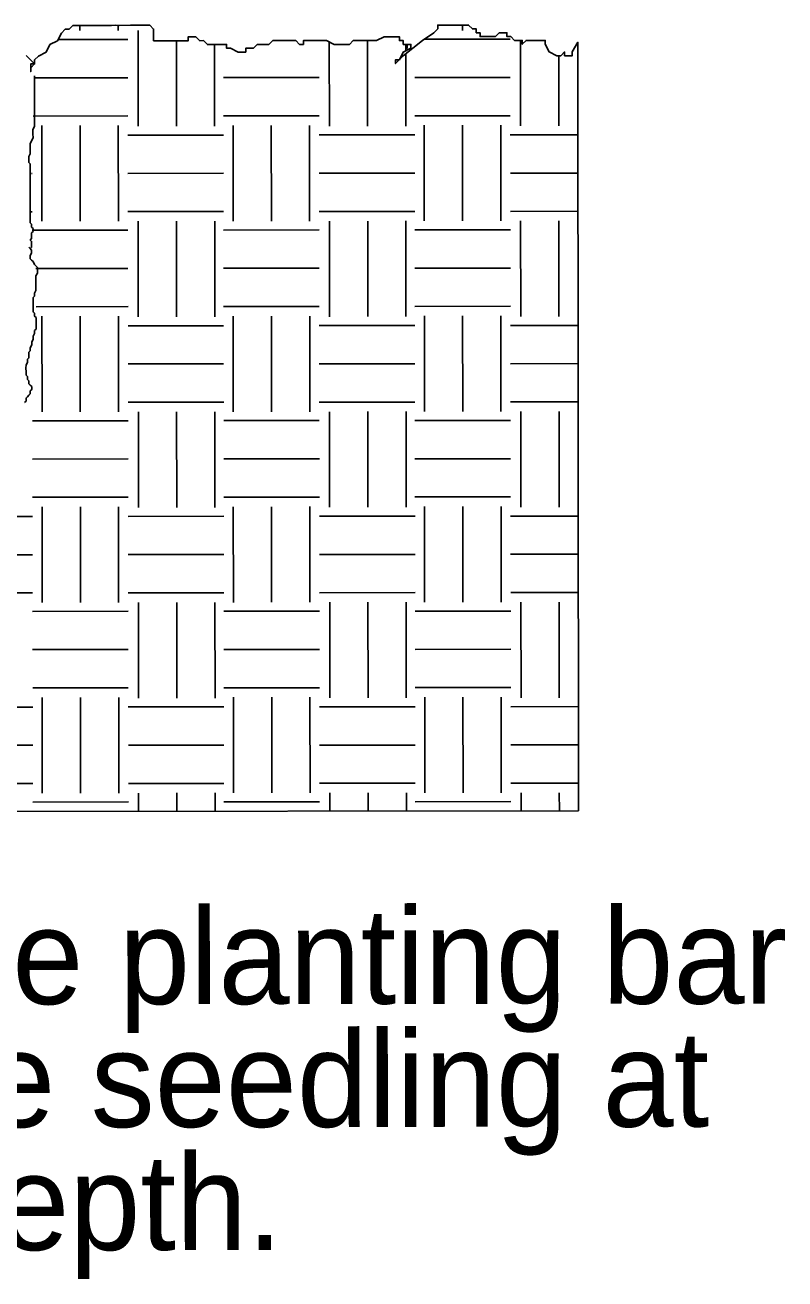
# Model space of a CAD drawing. Extents: x 1728110 to 1729925, y 1284214 to 1285339.
# Drawn here: x 1728835 to 1728889.8, y 1284892.4 to 1284982.8 of the extents above; entities that cross this region are included whole.
import ezdxf

# ---------------------------------------------------------------- set-up
doc = ezdxf.new("R2010")
doc.units = 0
doc.layers.add('Reforestation Detail CELL', color=7, linetype='Continuous')

msp = doc.modelspace()

# ---------------------------------------------------------------- linework, layer by layer
at = {"layer": 'Reforestation Detail CELL'}
for p, q in [((1728838.954, 1284982.743), (1728838.955, 1284982.364)), ((1728841.711, 1284982.746), (1728841.711, 1284982.366)), ((1728866.513, 1284982.764), (1728866.513, 1284982.385)), ((1728837.389, 1284981.722), (1728842.4, 1284981.726)), ((1728843.14, 1284982.367), (1728843.145, 1284975.478)), ((1728845.897, 1284981.64), (1728845.901, 1284975.48)), ((1728859.675, 1284981.651), (1728859.68, 1284975.49)), ((1728863.763, 1284981.742), (1728869.959, 1284981.747)), ((1728870.699, 1284981.659), (1728870.703, 1284975.498)), ((1728848.652, 1284981.366), (1728848.657, 1284975.482)), ((1728856.92, 1284981.545), (1728856.924, 1284975.488)), ((1728862.432, 1284981.376), (1728862.432, 1284980.915)), ((1728862.433, 1284980.693), (1728862.436, 1284975.493)), ((1728874.836, 1284981.524), (1728874.877, 1284926.15)), ((1728873.456, 1284980.553), (1728873.46, 1284975.501)), ((1728835.654, 1284978.965), (1728842.402, 1284978.971)), ((1728849.292, 1284978.976), (1728856.182, 1284978.981)), ((1728863.071, 1284978.986), (1728869.961, 1284978.991)), ((1728835.574, 1284976.209), (1728842.404, 1284976.215)), ((1728849.293, 1284976.22), (1728856.184, 1284976.225)), ((1728863.073, 1284976.23), (1728869.963, 1284976.235)), ((1728836.204, 1284975.521), (1728836.209, 1284968.631)), ((1728838.96, 1284975.522), (1728838.965, 1284968.633)), ((1728841.716, 1284975.525), (1728841.721, 1284968.635)), ((1728849.983, 1284975.531), (1728849.989, 1284968.641)), ((1728852.739, 1284975.534), (1728852.745, 1284968.643)), ((1728855.495, 1284975.535), (1728855.501, 1284968.646)), ((1728863.763, 1284975.542), (1728863.767, 1284968.652)), ((1728866.518, 1284975.544), (1728866.524, 1284968.654)), ((1728869.274, 1284975.546), (1728869.279, 1284968.656)), ((1728842.405, 1284974.836), (1728849.295, 1284974.841)), ((1728856.184, 1284974.847), (1728863.075, 1284974.852)), ((1728869.964, 1284974.857), (1728874.841, 1284974.861)), ((1728835.453, 1284972.075), (1728835.518, 1284972.075)), ((1728842.407, 1284972.08), (1728849.296, 1284972.085)), ((1728856.187, 1284972.091), (1728863.076, 1284972.096)), ((1728869.966, 1284972.102), (1728874.843, 1284972.105)), ((1728835.372, 1284969.32), (1728835.52, 1284969.319)), ((1728842.409, 1284969.324), (1728849.299, 1284969.329)), ((1728856.189, 1284969.335), (1728863.078, 1284969.341)), ((1728869.968, 1284969.345), (1728874.845, 1284969.349)), ((1728843.15, 1284968.636), (1728843.155, 1284961.747)), ((1728845.906, 1284968.638), (1728845.911, 1284961.749)), ((1728848.662, 1284968.64), (1728848.667, 1284961.75)), ((1728849.3, 1284968.001), (1728856.189, 1284968.006)), ((1728856.929, 1284968.647), (1728856.935, 1284961.757)), ((1728859.685, 1284968.648), (1728859.691, 1284961.759)), ((1728862.441, 1284968.651), (1728862.446, 1284961.761)), ((1728863.08, 1284968.011), (1728869.969, 1284968.016)), ((1728870.708, 1284968.657), (1728870.714, 1284961.767)), ((1728873.465, 1284968.659), (1728873.469, 1284961.769)), ((1728835.52, 1284967.99), (1728842.41, 1284967.994)), ((1728835.783, 1284965.234), (1728842.412, 1284965.239)), ((1728849.302, 1284965.245), (1728856.192, 1284965.25)), ((1728863.081, 1284965.255), (1728869.971, 1284965.26)), ((1728835.785, 1284962.478), (1728842.414, 1284962.484)), ((1728836.214, 1284961.789), (1728836.219, 1284954.9)), ((1728838.97, 1284961.791), (1728838.975, 1284954.902)), ((1728841.726, 1284961.794), (1728841.731, 1284954.904)), ((1728849.305, 1284962.489), (1728856.194, 1284962.494)), ((1728849.994, 1284961.8), (1728849.999, 1284954.91)), ((1728852.75, 1284961.801), (1728852.755, 1284954.912)), ((1728855.505, 1284961.804), (1728855.511, 1284954.914)), ((1728863.083, 1284962.499), (1728869.974, 1284962.504)), ((1728863.773, 1284961.81), (1728863.778, 1284954.921)), ((1728866.529, 1284961.813), (1728866.534, 1284954.922)), ((1728869.285, 1284961.814), (1728869.29, 1284954.925)), ((1728842.416, 1284961.105), (1728849.305, 1284961.11)), ((1728856.195, 1284961.115), (1728863.084, 1284961.12)), ((1728869.974, 1284961.126), (1728874.852, 1284961.13)), ((1728842.417, 1284958.349), (1728849.307, 1284958.354)), ((1728856.197, 1284958.359), (1728863.086, 1284958.364)), ((1728869.977, 1284958.37), (1728874.853, 1284958.374)), ((1728842.419, 1284955.593), (1728849.309, 1284955.598)), ((1728856.199, 1284955.603), (1728863.088, 1284955.61)), ((1728869.979, 1284955.614), (1728874.855, 1284955.618)), ((1728843.16, 1284954.905), (1728843.165, 1284948.015)), ((1728845.916, 1284954.907), (1728845.921, 1284948.018)), ((1728848.672, 1284954.909), (1728848.677, 1284948.019)), ((1728856.94, 1284954.915), (1728856.945, 1284948.026)), ((1728859.696, 1284954.917), (1728859.701, 1284948.028)), ((1728862.451, 1284954.92), (1728862.457, 1284948.029)), ((1728870.719, 1284954.926), (1728870.724, 1284948.036)), ((1728873.475, 1284954.928), (1728873.48, 1284948.038)), ((1728835.53, 1284954.258), (1728842.421, 1284954.263)), ((1728849.31, 1284954.269), (1728856.201, 1284954.274)), ((1728863.09, 1284954.28), (1728869.979, 1284954.285)), ((1728835.533, 1284951.502), (1728842.422, 1284951.507)), ((1728849.312, 1284951.513), (1728856.202, 1284951.518)), ((1728863.092, 1284951.524), (1728869.982, 1284951.529)), ((1728835.535, 1284948.746), (1728842.424, 1284948.752)), ((1728849.315, 1284948.757), (1728856.204, 1284948.763)), ((1728863.094, 1284948.768), (1728869.984, 1284948.773)), ((1728832.278, 1284947.367), (1728835.535, 1284947.369)), ((1728836.224, 1284948.058), (1728836.229, 1284941.168)), ((1728838.98, 1284948.06), (1728838.986, 1284941.171)), ((1728841.736, 1284948.062), (1728841.741, 1284941.173)), ((1728842.426, 1284947.374), (1728849.315, 1284947.379)), ((1728850.004, 1284948.068), (1728850.009, 1284941.179)), ((1728852.76, 1284948.07), (1728852.765, 1284941.181)), ((1728855.516, 1284948.073), (1728855.521, 1284941.183)), ((1728856.205, 1284947.384), (1728863.095, 1284947.389)), ((1728863.783, 1284948.079), (1728863.789, 1284941.189)), ((1728866.539, 1284948.082), (1728866.545, 1284941.191)), ((1728869.295, 1284948.083), (1728869.3, 1284941.193)), ((1728869.984, 1284947.394), (1728874.862, 1284947.399)), ((1728828.648, 1284944.608), (1728835.538, 1284944.613)), ((1728842.428, 1284944.618), (1728849.317, 1284944.623)), ((1728856.207, 1284944.628), (1728863.097, 1284944.633)), ((1728869.987, 1284944.638), (1728874.864, 1284944.643)), ((1728828.651, 1284941.852), (1728835.54, 1284941.857)), ((1728842.429, 1284941.862), (1728849.32, 1284941.867)), ((1728856.209, 1284941.872), (1728863.099, 1284941.877)), ((1728869.989, 1284941.882), (1728874.865, 1284941.887)), ((1728843.171, 1284941.174), (1728843.176, 1284934.284)), ((1728845.927, 1284941.176), (1728845.931, 1284934.286)), ((1728848.682, 1284941.178), (1728848.688, 1284934.288)), ((1728856.95, 1284941.184), (1728856.955, 1284934.294)), ((1728859.706, 1284941.186), (1728859.711, 1284934.297)), ((1728862.462, 1284941.188), (1728862.467, 1284934.298)), ((1728870.729, 1284941.194), (1728870.735, 1284934.305)), ((1728873.485, 1284941.196), (1728873.491, 1284934.307)), ((1728835.541, 1284940.527), (1728842.431, 1284940.532)), ((1728849.32, 1284940.537), (1728856.21, 1284940.542)), ((1728863.1, 1284940.548), (1728869.989, 1284940.554)), ((1728835.543, 1284937.771), (1728842.433, 1284937.776)), ((1728849.322, 1284937.782), (1728856.212, 1284937.786)), ((1728863.102, 1284937.792), (1728869.992, 1284937.797)), ((1728835.545, 1284935.015), (1728842.434, 1284935.021)), ((1728849.325, 1284935.025), (1728856.214, 1284935.031)), ((1728863.105, 1284935.036), (1728869.994, 1284935.042)), ((1728836.235, 1284934.327), (1728836.24, 1284927.437)), ((1728838.991, 1284934.329), (1728838.995, 1284927.439)), ((1728841.746, 1284934.331), (1728841.752, 1284927.442)), ((1728850.014, 1284934.337), (1728850.019, 1284927.447)), ((1728852.77, 1284934.339), (1728852.775, 1284927.45)), ((1728855.526, 1284934.341), (1728855.531, 1284927.452)), ((1728863.794, 1284934.347), (1728863.799, 1284927.458)), ((1728866.55, 1284934.349), (1728866.555, 1284927.46)), ((1728869.305, 1284934.352), (1728869.311, 1284927.462)), ((1728828.656, 1284933.632), (1728835.547, 1284933.638)), ((1728842.436, 1284933.643), (1728849.325, 1284933.648)), ((1728856.216, 1284933.653), (1728863.105, 1284933.658)), ((1728869.995, 1284933.663), (1728874.872, 1284933.667)), ((1728828.658, 1284930.877), (1728835.549, 1284930.882)), ((1728842.438, 1284930.887), (1728849.328, 1284930.892)), ((1728856.217, 1284930.897), (1728863.107, 1284930.902)), ((1728869.997, 1284930.907), (1728874.874, 1284930.911)), ((1728828.661, 1284928.121), (1728835.55, 1284928.126)), ((1728842.44, 1284928.131), (1728849.33, 1284928.136)), ((1728843.181, 1284927.442), (1728843.182, 1284926.127)), ((1728845.937, 1284927.445), (1728845.937, 1284926.129)), ((1728848.693, 1284927.447), (1728848.693, 1284926.13)), ((1728856.219, 1284928.141), (1728863.11, 1284928.146)), ((1728856.961, 1284927.453), (1728856.961, 1284926.137)), ((1728859.716, 1284927.455), (1728859.717, 1284926.139)), ((1728862.472, 1284927.457), (1728862.473, 1284926.141)), ((1728869.999, 1284928.151), (1728874.876, 1284928.155)), ((1728870.74, 1284927.463), (1728870.741, 1284926.147)), ((1728873.495, 1284927.465), (1728873.497, 1284926.15)), ((1728835.552, 1284926.796), (1728842.441, 1284926.801)), ((1728849.33, 1284926.806), (1728856.221, 1284926.811)), ((1728863.11, 1284926.816), (1728870, 1284926.821)), ((1728792.974, 1284926.089), (1728874.877, 1284926.15))]:
    msp.add_line(p, q, dxfattribs=at)
for points in [[(1728835.08, 1284980.576), (1728835.131, 1284980.525), (1728835.685, 1284979.971), (1728835.408, 1284979.971), (1728835.409, 1284979.694), (1728835.408, 1284979.418), (1728835.409, 1284979.694), (1728835.685, 1284979.971), (1728835.685, 1284980.249), (1728835.962, 1284980.526), (1728836.515, 1284980.803), (1728836.791, 1284981.357), (1728837.344, 1284981.634), (1728837.621, 1284982.188), (1728837.896, 1284982.465), (1728838.174, 1284982.465), (1728838.45, 1284982.743), (1728838.727, 1284982.743), (1728839.003, 1284982.744), (1728839.557, 1284982.744), (1728839.834, 1284982.744), (1728840.387, 1284982.744), (1728840.663, 1284982.745), (1728840.94, 1284982.745), (1728841.217, 1284982.745), (1728841.493, 1284982.746), (1728841.77, 1284982.745), (1728842.6, 1284982.746), (1728842.878, 1284982.746), (1728843.154, 1284982.746), (1728843.431, 1284982.747), (1728843.707, 1284982.747), (1728843.984, 1284982.747), (1728844.26, 1284982.47), (1728844.261, 1284981.916), (1728844.261, 1284981.639), (1728844.539, 1284981.64), (1728845.091, 1284981.64), (1728845.645, 1284981.64), (1728845.921, 1284981.641), (1728846.199, 1284981.641), (1728846.475, 1284981.64), (1728846.752, 1284981.641), (1728846.752, 1284981.918), (1728847.027, 1284981.918), (1728847.305, 1284981.917), (1728847.582, 1284981.641), (1728847.859, 1284981.642), (1728848.135, 1284981.365), (1728848.413, 1284981.366), (1728848.688, 1284981.366), (1728848.966, 1284981.366), (1728849.242, 1284981.366), (1728849.519, 1284981.367), (1728849.519, 1284981.089), (1728849.797, 1284981.089), (1728850.35, 1284980.814), (1728850.626, 1284980.814), (1728850.903, 1284980.815), (1728850.903, 1284981.09), (1728851.18, 1284981.09), (1728851.456, 1284981.09), (1728851.733, 1284981.368), (1728852.009, 1284981.369), (1728852.286, 1284981.369), (1728852.563, 1284981.368), (1728852.839, 1284981.646), (1728853.393, 1284981.645), (1728853.67, 1284981.646), (1728853.946, 1284981.646), (1728854.222, 1284981.647), (1728854.5, 1284981.647), (1728854.777, 1284981.371), (1728855.053, 1284981.37), (1728855.052, 1284981.647), (1728855.33, 1284981.648), (1728855.607, 1284981.647), (1728855.883, 1284981.647), (1728856.16, 1284981.648), (1728856.436, 1284981.648), (1728856.713, 1284981.648), (1728857.266, 1284981.372), (1728857.544, 1284981.372), (1728857.819, 1284981.373), (1728858.097, 1284981.373), (1728858.374, 1284981.373), (1728858.65, 1284981.65), (1728858.927, 1284981.65), (1728859.204, 1284981.65), (1728859.479, 1284981.65), (1728859.757, 1284981.651), (1728860.31, 1284981.651), (1728860.863, 1284981.928)], [(1728860.863, 1284981.928), (1728860.31, 1284981.651), (1728859.757, 1284981.651), (1728859.479, 1284981.65), (1728859.204, 1284981.65), (1728858.927, 1284981.65), (1728858.65, 1284981.65), (1728858.374, 1284981.373), (1728858.097, 1284981.373), (1728857.819, 1284981.373), (1728857.544, 1284981.372), (1728857.266, 1284981.372), (1728856.713, 1284981.648), (1728856.436, 1284981.648), (1728856.16, 1284981.648), (1728855.883, 1284981.647), (1728855.607, 1284981.647), (1728855.33, 1284981.648), (1728855.052, 1284981.647), (1728855.053, 1284981.37), (1728854.777, 1284981.371), (1728854.5, 1284981.647), (1728854.222, 1284981.647), (1728853.946, 1284981.646), (1728853.67, 1284981.646), (1728853.393, 1284981.645), (1728852.839, 1284981.646), (1728852.563, 1284981.368), (1728852.286, 1284981.369), (1728852.009, 1284981.369), (1728851.733, 1284981.368), (1728851.456, 1284981.09), (1728851.18, 1284981.09), (1728850.903, 1284981.09), (1728850.903, 1284980.815), (1728850.626, 1284980.814), (1728850.35, 1284980.814), (1728849.797, 1284981.089), (1728849.519, 1284981.089), (1728849.519, 1284981.367), (1728849.242, 1284981.366), (1728848.966, 1284981.366), (1728848.688, 1284981.366), (1728848.413, 1284981.366), (1728848.135, 1284981.365), (1728847.859, 1284981.642), (1728847.582, 1284981.641), (1728847.305, 1284981.917), (1728847.027, 1284981.918), (1728846.752, 1284981.918), (1728846.752, 1284981.641), (1728846.475, 1284981.64), (1728846.199, 1284981.641), (1728845.921, 1284981.641), (1728845.645, 1284981.64), (1728845.091, 1284981.64), (1728844.539, 1284981.64), (1728844.261, 1284981.639), (1728844.261, 1284981.916), (1728844.26, 1284982.47), (1728843.984, 1284982.747), (1728843.707, 1284982.747), (1728843.431, 1284982.747), (1728843.154, 1284982.746), (1728842.878, 1284982.746), (1728842.6, 1284982.746), (1728841.77, 1284982.745), (1728841.493, 1284982.746), (1728841.217, 1284982.745), (1728840.94, 1284982.745), (1728840.663, 1284982.745), (1728840.387, 1284982.744), (1728839.834, 1284982.744), (1728839.557, 1284982.744), (1728839.003, 1284982.744), (1728838.727, 1284982.743), (1728838.45, 1284982.743), (1728838.174, 1284982.465), (1728837.896, 1284982.465), (1728837.621, 1284982.188), (1728837.344, 1284981.634), (1728836.791, 1284981.357), (1728836.515, 1284980.803), (1728835.962, 1284980.526), (1728835.685, 1284980.249), (1728835.685, 1284979.971), (1728835.409, 1284979.694), (1728835.408, 1284979.418), (1728835.409, 1284979.694), (1728835.408, 1284979.971), (1728835.685, 1284979.971), (1728835.131, 1284980.525), (1728835.08, 1284980.576)], [(1728860.863, 1284981.928), (1728861.417, 1284981.929), (1728861.694, 1284981.929), (1728861.97, 1284981.929), (1728861.971, 1284981.653), (1728862.247, 1284981.652), (1728862.247, 1284981.376), (1728862.247, 1284981.652), (1728862.247, 1284981.376), (1728862.524, 1284981.376), (1728862.525, 1284981.099), (1728862.524, 1284981.376), (1728862.801, 1284981.376), (1728862.801, 1284981.099), (1728862.248, 1284980.823), (1728861.972, 1284980.268), (1728861.695, 1284980.269), (1728861.696, 1284979.99), (1728862.248, 1284980.545), (1728863.631, 1284981.654), (1728864.46, 1284982.209), (1728864.737, 1284982.485), (1728864.737, 1284982.762), (1728865.013, 1284982.763), (1728865.567, 1284982.763), (1728865.843, 1284982.763), (1728866.121, 1284982.764), (1728866.397, 1284982.764), (1728866.673, 1284982.764), (1728866.951, 1284982.764), (1728867.227, 1284982.487), (1728867.504, 1284982.488), (1728867.504, 1284982.21), (1728867.781, 1284982.21), (1728867.781, 1284981.933), (1728868.058, 1284981.934), (1728868.335, 1284981.934), (1728868.888, 1284981.935), (1728869.164, 1284982.212), (1728869.441, 1284982.212), (1728869.717, 1284982.212), (1728869.717, 1284981.935), (1728869.995, 1284981.935), (1728870.272, 1284981.659), (1728870.549, 1284981.659), (1728870.825, 1284981.658), (1728870.825, 1284981.382), (1728871.101, 1284981.659), (1728871.378, 1284981.659), (1728871.655, 1284981.659), (1728871.932, 1284981.66), (1728872.208, 1284981.66), (1728872.485, 1284981.66), (1728872.486, 1284981.384), (1728872.763, 1284980.831), (1728873.316, 1284980.553), (1728873.593, 1284980.554), (1728873.869, 1284980.831), (1728873.869, 1284980.554), (1728874.146, 1284980.554), (1728874.423, 1284980.555), (1728874.423, 1284980.832), (1728874.836, 1284981.524), (1728874.836, 1284981.524)], [(1728874.836, 1284981.524), (1728874.836, 1284981.524), (1728874.423, 1284980.832), (1728874.423, 1284980.555), (1728874.146, 1284980.554), (1728873.869, 1284980.554), (1728873.869, 1284980.831), (1728873.593, 1284980.554), (1728873.316, 1284980.553), (1728872.763, 1284980.831), (1728872.486, 1284981.384), (1728872.485, 1284981.66), (1728872.208, 1284981.66), (1728871.932, 1284981.66), (1728871.655, 1284981.659), (1728871.378, 1284981.659), (1728871.101, 1284981.659), (1728870.825, 1284981.382), (1728870.825, 1284981.658), (1728870.549, 1284981.659), (1728870.272, 1284981.659), (1728869.995, 1284981.935), (1728869.717, 1284981.935), (1728869.717, 1284982.212), (1728869.441, 1284982.212), (1728869.164, 1284982.212), (1728868.888, 1284981.935), (1728868.335, 1284981.934), (1728868.058, 1284981.934), (1728867.781, 1284981.933), (1728867.781, 1284982.21), (1728867.504, 1284982.21), (1728867.504, 1284982.488), (1728867.227, 1284982.487), (1728866.951, 1284982.764), (1728866.673, 1284982.764), (1728866.397, 1284982.764), (1728866.121, 1284982.764), (1728865.843, 1284982.763), (1728865.567, 1284982.763), (1728865.013, 1284982.763), (1728864.737, 1284982.762), (1728864.737, 1284982.485), (1728864.46, 1284982.209), (1728863.631, 1284981.654), (1728862.248, 1284980.545), (1728861.696, 1284979.99), (1728861.695, 1284980.269), (1728861.972, 1284980.268), (1728862.248, 1284980.823), (1728862.801, 1284981.099), (1728862.801, 1284981.376), (1728862.524, 1284981.376), (1728862.525, 1284981.099), (1728862.524, 1284981.376), (1728862.247, 1284981.376), (1728862.247, 1284981.652), (1728862.247, 1284981.376), (1728862.247, 1284981.652), (1728861.971, 1284981.653), (1728861.97, 1284981.929), (1728861.694, 1284981.929), (1728861.417, 1284981.929), (1728860.863, 1284981.928)], [(1728835.669, 1284979.11), (1728835.669, 1284978.151), (1728835.669, 1284977.944), (1728835.669, 1284977.737), (1728835.67, 1284977.53), (1728835.67, 1284977.323), (1728835.67, 1284977.116), (1728835.67, 1284976.908), (1728835.67, 1284976.701), (1728835.671, 1284976.494), (1728835.67, 1284976.287), (1728835.67, 1284976.08), (1728835.671, 1284975.873), (1728835.671, 1284975.666), (1728835.672, 1284975.458), (1728835.568, 1284975.252), (1728835.568, 1284974.941), (1728835.569, 1284974.631), (1728835.465, 1284974.423), (1728835.361, 1284974.216), (1728835.362, 1284974.01), (1728835.362, 1284973.803), (1728835.362, 1284973.491), (1728835.259, 1284973.285), (1728835.259, 1284973.077), (1728835.259, 1284972.87), (1728835.362, 1284972.766), (1728835.363, 1284972.456), (1728835.362, 1284972.25), (1728835.363, 1284972.041), (1728835.363, 1284971.731), (1728835.363, 1284971.524), (1728835.363, 1284971.317), (1728835.364, 1284971.111), (1728835.363, 1284970.903), (1728835.363, 1284970.695), (1728835.364, 1284970.386), (1728835.364, 1284970.075), (1728835.364, 1284969.867), (1728835.364, 1284969.661), (1728835.364, 1284969.453), (1728835.365, 1284969.246), (1728835.366, 1284969.039), (1728835.365, 1284968.832), (1728835.366, 1284968.522), (1728835.469, 1284968.418), (1728835.469, 1284968.211), (1728835.574, 1284968.107), (1728835.574, 1284967.9), (1728835.469, 1284967.797), (1728835.469, 1284967.59), (1728835.469, 1284967.382), (1728835.366, 1284967.279), (1728835.47, 1284967.176), (1728835.47, 1284966.968), (1728835.47, 1284966.761), (1728835.367, 1284966.658), (1728835.367, 1284966.658), (1728835.47, 1284966.761)], [(1728835.368, 1284966.14), (1728835.47, 1284966.348), (1728835.47, 1284966.555), (1728835.367, 1284966.658), (1728835.264, 1284966.761)], [(1728834.962, 1284955.579), (1728835.065, 1284955.682), (1728835.064, 1284955.889), (1728835.168, 1284955.993), (1728835.272, 1284956.097), (1728835.374, 1284956.2), (1728835.374, 1284956.407), (1728835.478, 1284956.511), (1728835.478, 1284956.718), (1728835.374, 1284956.821), (1728835.271, 1284956.925), (1728835.27, 1284957.131), (1728835.168, 1284957.236), (1728835.167, 1284957.442), (1728835.064, 1284957.547), (1728835.064, 1284957.754), (1728835.063, 1284958.063), (1728835.064, 1284958.271), (1728835.167, 1284958.478), (1728835.166, 1284958.686), (1728835.27, 1284958.789), (1728835.27, 1284958.997), (1728835.269, 1284959.203), (1728835.372, 1284959.307), (1728835.372, 1284959.513), (1728835.475, 1284959.721), (1728835.475, 1284959.928), (1728835.58, 1284960.136), (1728835.579, 1284960.342), (1728835.683, 1284960.549), (1728835.682, 1284960.755), (1728835.786, 1284960.86), (1728835.785, 1284961.067), (1728835.786, 1284961.275), (1728835.785, 1284961.481), (1728835.785, 1284961.688), (1728835.682, 1284961.791), (1728835.681, 1284961.999), (1728835.578, 1284962.102), (1728835.578, 1284962.309), (1728835.578, 1284962.516), (1728835.578, 1284962.724), (1728835.578, 1284962.931), (1728835.577, 1284963.137), (1728835.68, 1284963.241), (1728835.68, 1284963.448), (1728835.783, 1284963.655), (1728835.783, 1284963.863), (1728835.783, 1284964.07), (1728835.783, 1284964.277), (1728835.783, 1284964.484), (1728835.783, 1284964.691), (1728835.886, 1284964.898), (1728835.886, 1284965.105), (1728835.886, 1284965.312), (1728835.782, 1284965.415), (1728835.678, 1284965.518), (1728835.575, 1284965.727)], [(1728835.575, 1284965.727), (1728835.471, 1284965.83), (1728835.368, 1284965.932), (1728835.368, 1284966.14)]]:
    msp.add_lwpolyline(points, dxfattribs=at)

# ---------------------------------------------------------------- texts
for s, p in [('2. Remove planting bar ', (1728794.65, 1284912.201)), (' and place seedling at ', (1728794.656, 1284903.343)), (' correct depth.', (1728794.663, 1284894.485))]:
    msp.add_text(s, height=6.88975, rotation=0.04293, dxfattribs=at).set_placement(p)

doc.saveas('drawing.dxf')
